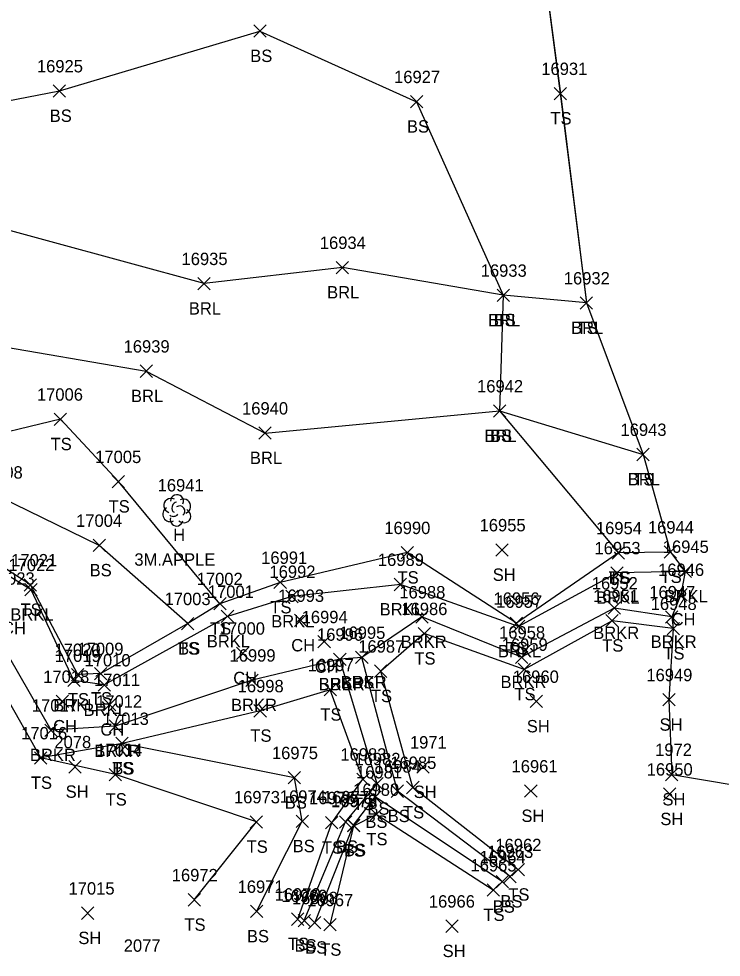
# Model space of a CAD drawing. Extents: x 1482574 to 1485769, y 580696 to 595649.
# Drawn here: x 1485016 to 1485129.5, y 582871.1 to 583022.8 of the extents above; entities that cross this region are included whole.
import ezdxf

# ---------------------------------------------------------------- set-up
doc = ezdxf.new("R2010")
doc.units = 0
for name, color, linetype in [('L_A', 7, 'Continuous'), ('L_C', 7, 'Continuous'), ('L_I', 7, 'Continuous'), ('L_TIC', 7, 'Continuous'), ('LABL', 7, 'Continuous'), ('LAWE', 7, 'Continuous'), ('LELB', 7, 'Continuous'), ('LSOGP', 7, 'Continuous'), ('LTD', 7, 'Continuous')]:
    doc.layers.add(name, color=color, linetype=linetype)

msp = doc.modelspace()

# ---------------------------------------------------------------- linework, layer by layer
at = {"layer": 'L_TIC'}
for points in [[(1485053.96, 583019.83), (1485055.96, 583021.83)], [(1485055.96, 583019.83), (1485053.96, 583021.83)], [(1485021.56, 583010.15), (1485023.56, 583012.15)], [(1485023.56, 583010.15), (1485021.56, 583012.15)], [(1485102.51, 583009.73), (1485104.51, 583011.73)], [(1485104.51, 583009.73), (1485102.51, 583011.73)], [(1485079.29, 583008.42), (1485081.29, 583010.42)], [(1485081.29, 583008.42), (1485079.29, 583010.42)], [(1485067.29, 582981.61), (1485069.29, 582983.61)], [(1485069.29, 582981.61), (1485067.29, 582983.61)], [(1485044.94, 582979.01), (1485046.94, 582981.01)], [(1485046.94, 582979.01), (1485044.94, 582981.01)], [(1485093.29, 582977.12), (1485095.29, 582979.12)], [(1485095.29, 582977.12), (1485093.29, 582979.12)], [(1485093.29, 582977.12), (1485095.29, 582979.12)], [(1485095.29, 582977.12), (1485093.29, 582979.12)], [(1485106.72, 582975.88), (1485108.72, 582977.88)], [(1485108.72, 582975.88), (1485106.72, 582977.88)], [(1485106.72, 582975.88), (1485108.72, 582977.88)], [(1485108.72, 582975.88), (1485106.72, 582977.88)], [(1485035.59, 582964.86), (1485037.59, 582966.86)], [(1485037.59, 582964.86), (1485035.59, 582966.86)], [(1485021.73, 582957.09), (1485023.73, 582959.09)], [(1485023.73, 582957.09), (1485021.73, 582959.09)], [(1485092.7, 582958.43), (1485094.7, 582960.43)], [(1485094.7, 582958.43), (1485092.7, 582960.43)], [(1485092.7, 582958.43), (1485094.7, 582960.43)], [(1485094.7, 582958.43), (1485092.7, 582960.43)], [(1485054.81, 582954.85), (1485056.81, 582956.85)], [(1485056.81, 582954.85), (1485054.81, 582956.85)], [(1485115.88, 582951.39), (1485117.88, 582953.39)], [(1485117.88, 582951.39), (1485115.88, 582953.39)], [(1485115.88, 582951.39), (1485117.88, 582953.39)], [(1485117.88, 582951.39), (1485115.88, 582953.39)], [(1485031.1, 582947.01), (1485033.1, 582949.01)], [(1485033.1, 582947.01), (1485031.1, 582949.01)], [(1485028.01, 582936.7), (1485030.01, 582938.7)], [(1485030.01, 582936.7), (1485028.01, 582938.7)], [(1485093.1, 582935.97), (1485095.1, 582937.97)], [(1485095.1, 582935.97), (1485093.1, 582937.97)], [(1485077.79, 582935.53), (1485079.79, 582937.53)], [(1485079.79, 582935.53), (1485077.79, 582937.53)], [(1485111.9, 582935.5), (1485113.9, 582937.5)], [(1485113.9, 582935.5), (1485111.9, 582937.5)], [(1485111.9, 582935.5), (1485113.9, 582937.5)], [(1485113.9, 582935.5), (1485111.9, 582937.5)], [(1485120.3, 582935.63), (1485122.3, 582937.63)], [(1485122.3, 582935.63), (1485120.3, 582937.63)], [(1485111.68, 582932.26), (1485113.68, 582934.26)], [(1485113.68, 582932.26), (1485111.68, 582934.26)], [(1485122.7, 582932.49), (1485124.7, 582934.49)], [(1485124.7, 582932.49), (1485122.7, 582934.49)], [(1485016.87, 582930.31), (1485018.87, 582932.31)], [(1485018.87, 582930.31), (1485016.87, 582932.31)], [(1485057.24, 582930.71), (1485059.24, 582932.71)], [(1485059.24, 582930.71), (1485057.24, 582932.71)], [(1485076.68, 582930.38), (1485078.68, 582932.38)], [(1485078.68, 582930.38), (1485076.68, 582932.38)], [(1485016.99, 582929.54), (1485018.99, 582931.54)], [(1485018.99, 582929.54), (1485016.99, 582931.54)], [(1485059.14, 582928.44), (1485061.14, 582930.44)], [(1485061.14, 582928.44), (1485059.14, 582930.44)], [(1485122.01, 582928.76), (1485124.01, 582930.76)], [(1485124.01, 582928.76), (1485122.01, 582930.76)], [(1485047.5, 582927.28), (1485049.5, 582929.28)], [(1485049.5, 582927.28), (1485047.5, 582929.28)], [(1485047.5, 582927.28), (1485049.5, 582929.28)], [(1485049.5, 582927.28), (1485047.5, 582929.28)], [(1485048.73, 582925.22), (1485050.73, 582927.22)], [(1485050.73, 582925.22), (1485048.73, 582927.22)], [(1485080.14, 582925.13), (1485082.14, 582927.13)], [(1485082.14, 582925.13), (1485080.14, 582927.13)], [(1485111.24, 582926.58), (1485113.24, 582928.58)], [(1485113.24, 582926.58), (1485111.24, 582928.58)], [(1485120.53, 582925.14), (1485122.53, 582927.14)], [(1485122.53, 582925.14), (1485120.53, 582927.14)], [(1485042.31, 582924.05), (1485044.31, 582926.05)], [(1485044.31, 582924.05), (1485042.31, 582926.05)], [(1485042.31, 582924.05), (1485044.31, 582926.05)], [(1485044.31, 582924.05), (1485042.31, 582926.05)], [(1485060.54, 582924.57), (1485062.54, 582926.57)], [(1485062.54, 582924.57), (1485060.54, 582926.57)], [(1485095.41, 582924.11), (1485097.41, 582926.11)], [(1485097.41, 582924.11), (1485095.41, 582926.11)], [(1485095.77, 582923.61), (1485097.77, 582925.61)], [(1485097.77, 582923.61), (1485095.77, 582925.61)], [(1485110.87, 582924.53), (1485112.87, 582926.53)], [(1485112.87, 582924.53), (1485110.87, 582926.53)], [(1485080.52, 582922.44), (1485082.52, 582924.44)], [(1485082.52, 582922.44), (1485080.52, 582924.44)], [(1485120.76, 582923.26), (1485122.76, 582925.26)], [(1485122.76, 582923.26), (1485120.76, 582925.26)], [(1485064.35, 582921.12), (1485066.35, 582923.12)], [(1485066.35, 582921.12), (1485064.35, 582923.12)], [(1485051.17, 582919.27), (1485053.17, 582921.27)], [(1485053.17, 582919.27), (1485051.17, 582921.27)], [(1485066.88, 582918.29), (1485068.88, 582920.29)], [(1485068.88, 582918.29), (1485066.88, 582920.29)], [(1485066.88, 582918.29), (1485068.88, 582920.29)], [(1485068.88, 582918.29), (1485066.88, 582920.29)], [(1485070.44, 582918.59), (1485072.44, 582920.59)], [(1485072.44, 582918.59), (1485070.44, 582920.59)], [(1485070.44, 582918.59), (1485072.44, 582920.59)], [(1485072.44, 582918.59), (1485070.44, 582920.59)], [(1485096.26, 582918.63), (1485098.26, 582920.63)], [(1485098.26, 582918.63), (1485096.26, 582920.63)], [(1485073.5, 582916.37), (1485075.5, 582918.37)], [(1485075.5, 582916.37), (1485073.5, 582918.37)], [(1485073.5, 582916.37), (1485075.5, 582918.37)], [(1485075.5, 582916.37), (1485073.5, 582918.37)], [(1485096.69, 582916.66), (1485098.69, 582918.66)], [(1485098.69, 582916.66), (1485096.69, 582918.66)], [(1485023.91, 582914.87), (1485025.91, 582916.87)], [(1485025.91, 582914.87), (1485023.91, 582916.87)], [(1485024.52, 582915.83), (1485026.52, 582917.83)], [(1485026.52, 582915.83), (1485024.52, 582917.83)], [(1485028.24, 582915.98), (1485030.24, 582917.98)], [(1485030.24, 582915.98), (1485028.24, 582917.98)], [(1485052.71, 582914.91), (1485054.71, 582916.91)], [(1485054.71, 582914.91), (1485052.71, 582916.91)], [(1485028.82, 582914.14), (1485030.82, 582916.14)], [(1485030.82, 582914.14), (1485028.82, 582916.14)], [(1485065.33, 582913.37), (1485067.33, 582915.37)], [(1485067.33, 582913.37), (1485065.33, 582915.37)], [(1485065.33, 582913.37), (1485067.33, 582915.37)], [(1485067.33, 582913.37), (1485065.33, 582915.37)], [(1485022.05, 582911.48), (1485024.05, 582913.48)], [(1485024.05, 582911.48), (1485022.05, 582913.48)], [(1485098.62, 582911.48), (1485100.62, 582913.48)], [(1485100.62, 582911.48), (1485098.62, 582913.48)], [(1485120.07, 582911.75), (1485122.07, 582913.75)], [(1485122.07, 582911.75), (1485120.07, 582913.75)], [(1485029.69, 582910.95), (1485031.69, 582912.95)], [(1485031.69, 582910.95), (1485029.69, 582912.95)], [(1485054.01, 582909.96), (1485056.01, 582911.96)], [(1485056.01, 582909.96), (1485054.01, 582911.96)], [(1485030.6, 582907.48), (1485032.6, 582909.48)], [(1485032.6, 582907.48), (1485030.6, 582909.48)], [(1485020.21, 582906.83), (1485022.21, 582908.83)], [(1485022.21, 582906.83), (1485020.21, 582908.83)], [(1485031.68, 582904.68), (1485033.68, 582906.68)], [(1485033.68, 582904.68), (1485031.68, 582906.68)], [(1485031.68, 582904.68), (1485033.68, 582906.68)], [(1485033.68, 582904.68), (1485031.68, 582906.68)], [(1485018.54, 582902.35), (1485020.54, 582904.35)], [(1485020.54, 582902.35), (1485018.54, 582904.35)], [(1485018.54, 582902.35), (1485020.54, 582904.35)], [(1485020.54, 582902.35), (1485018.54, 582904.35)], [(1485024.08, 582900.91), (1485026.08, 582902.91)], [(1485026.08, 582900.91), (1485024.08, 582902.91)], [(1485080.33, 582900.87), (1485082.33, 582902.87)], [(1485082.33, 582900.87), (1485080.33, 582902.87)], [(1485030.62, 582899.65), (1485032.62, 582901.65)], [(1485032.62, 582899.65), (1485030.62, 582901.65)], [(1485120.53, 582899.67), (1485122.53, 582901.67)], [(1485122.53, 582899.67), (1485120.53, 582901.67)], [(1485059.54, 582899.15), (1485061.54, 582901.15)], [(1485061.54, 582899.15), (1485059.54, 582901.15)], [(1485070.61, 582898.91), (1485072.61, 582900.91)], [(1485072.61, 582898.91), (1485070.61, 582900.91)], [(1485072.89, 582898.17), (1485074.89, 582900.17)], [(1485074.89, 582898.17), (1485072.89, 582900.17)], [(1485072.89, 582898.17), (1485074.89, 582900.17)], [(1485074.89, 582898.17), (1485072.89, 582900.17)], [(1485076.18, 582896.98), (1485078.18, 582898.98)], [(1485078.18, 582896.98), (1485076.18, 582898.98)], [(1485078.68, 582897.57), (1485080.68, 582899.57)], [(1485080.68, 582897.57), (1485078.68, 582899.57)], [(1485097.75, 582897), (1485099.75, 582899)], [(1485099.75, 582897), (1485097.75, 582899)], [(1485120.19, 582896.49), (1485122.19, 582898.49)], [(1485122.19, 582896.49), (1485120.19, 582898.49)], [(1485072.57, 582896.04), (1485074.57, 582898.04)], [(1485074.57, 582896.04), (1485072.57, 582898.04)], [(1485072.57, 582896.04), (1485074.57, 582898.04)], [(1485074.57, 582896.04), (1485072.57, 582898.04)], [(1485072.76, 582893.23), (1485074.76, 582895.23)], [(1485074.76, 582893.23), (1485072.76, 582895.23)], [(1485072.76, 582893.23), (1485074.76, 582895.23)], [(1485074.76, 582893.23), (1485072.76, 582895.23)], [(1485053.41, 582892.01), (1485055.41, 582894.01)], [(1485055.41, 582892.01), (1485053.41, 582894.01)], [(1485060.82, 582892.11), (1485062.82, 582894.11)], [(1485062.82, 582892.11), (1485060.82, 582894.11)], [(1485065.58, 582891.87), (1485067.58, 582893.87)], [(1485067.58, 582891.87), (1485065.58, 582893.87)], [(1485067.81, 582892.01), (1485069.81, 582894.01)], [(1485069.81, 582892.01), (1485067.81, 582894.01)], [(1485069.1, 582891.46), (1485071.1, 582893.46)], [(1485071.1, 582891.46), (1485069.1, 582893.46)], [(1485069.12, 582891.39), (1485071.12, 582893.39)], [(1485071.12, 582891.39), (1485069.12, 582893.39)], [(1485095.7, 582884.28), (1485097.7, 582886.28)], [(1485097.7, 582884.28), (1485095.7, 582886.28)], [(1485094.4, 582883.18), (1485096.4, 582885.18)], [(1485096.4, 582883.18), (1485094.4, 582885.18)], [(1485093.15, 582882.33), (1485095.15, 582884.33)], [(1485095.15, 582882.33), (1485093.15, 582884.33)], [(1485091.68, 582881), (1485093.68, 582883)], [(1485093.68, 582881), (1485091.68, 582883)], [(1485043.36, 582879.41), (1485045.36, 582881.41)], [(1485045.36, 582879.41), (1485043.36, 582881.41)], [(1485026.14, 582877.26), (1485028.14, 582879.26)], [(1485028.14, 582877.26), (1485026.14, 582879.26)], [(1485053.43, 582877.54), (1485055.43, 582879.54)], [(1485055.43, 582877.54), (1485053.43, 582879.54)], [(1485060.07, 582876.29), (1485062.07, 582878.29)], [(1485062.07, 582876.29), (1485060.07, 582878.29)], [(1485061.13, 582876.05), (1485063.13, 582878.05)], [(1485063.13, 582876.05), (1485061.13, 582878.05)], [(1485062.83, 582875.71), (1485064.83, 582877.71)], [(1485064.83, 582875.71), (1485062.83, 582877.71)], [(1485065.3, 582875.38), (1485067.3, 582877.38)], [(1485067.3, 582875.38), (1485065.3, 582877.38)], [(1485085.01, 582875.16), (1485087.01, 582877.16)], [(1485087.01, 582875.16), (1485085.01, 582877.16)]]:
    msp.add_lwpolyline(points, dxfattribs=at)
at = {"layer": 'LABL'}
msp.add_lwpolyline([(1485107.72, 582976.88), (1485094.29, 582978.12), (1485068.29, 582982.61), (1485045.94, 582980.01), (1485007.9, 582990.37), (1485001, 582981.38), (1485010.19, 582970.36), (1485036.59, 582965.86), (1485055.81, 582955.85), (1485093.7, 582959.43), (1485116.88, 582952.39)], dxfattribs=at)
at = {"layer": 'LAWE'}
for points in [[(1485123.7, 582933.49), (1485112.68, 582933.26), (1485096.77, 582924.61), (1485077.68, 582931.38), (1485060.14, 582929.44), (1485049.73, 582926.22), (1485029.82, 582915.14), (1485024.91, 582915.87), (1485017.99, 582930.54), (1485007.2, 582937.17), (1485001.22, 582943.38), (1484992.98, 582957.36), (1484981.1, 582966.08), (1484969.65, 582970.81), (1484966.84, 582974.91), (1484969.87, 582981.75), (1484967.99, 582987.69), (1484963.16, 582993.41), (1484943.08, 582999.77)], [(1485121.53, 582926.14), (1485112.24, 582927.58), (1485097.26, 582919.63), (1485081.14, 582926.13), (1485071.44, 582919.59), (1485067.88, 582919.29), (1485053.71, 582915.91), (1485031.6, 582908.48), (1485021.21, 582907.83), (1485010.94, 582925.67), (1485004.69, 582933.37), (1484995.82, 582942.92), (1484986.83, 582954.25), (1484977.2, 582963.34), (1484963.68, 582969.01), (1484961.04, 582975.02), (1484964.44, 582984), (1484958.58, 582987.66), (1484946.85, 582991.58)]]:
    msp.add_lwpolyline(points, dxfattribs=at)
at = {"layer": 'LELB'}
for points in [[(1485100.1, 583036.87), (1485103.51, 583010.73), (1485107.72, 582976.88), (1485116.88, 582952.39), (1485121.3, 582936.63), (1485112.9, 582936.5), (1485096.41, 582925.11), (1485078.79, 582936.53), (1485058.24, 582931.71), (1485048.5, 582928.28), (1485032.1, 582948.01), (1485022.73, 582958.09), (1485007.54, 582954.43), (1484998.15, 582959.34)], [(1484952.16, 583010.58), (1484991.93, 583005.23), (1485022.56, 583011.15), (1485054.96, 583020.83), (1485080.29, 583009.42), (1485094.29, 582978.12), (1485093.7, 582959.43), (1485112.9, 582936.5)], [(1485048.5, 582928.28), (1485043.31, 582925.05), (1485029.24, 582916.98), (1485025.52, 582916.83), (1485017.87, 582931.31), (1485007.46, 582938.06), (1485003.43, 582945.8), (1484998.15, 582959.34), (1484981.68, 582967.5), (1484970.06, 582971.15), (1484968.16, 582975.1), (1484970.87, 582981.38), (1484969.06, 582988.39), (1484964.08, 582995.64), (1484942.52, 583002.84)], [(1485066.33, 582914.37), (1485055.01, 582910.96), (1485032.68, 582905.68), (1485019.54, 582903.35), (1485007.57, 582924.48), (1485005.74, 582928.29), (1485002.98, 582932.23), (1484994.58, 582942.15), (1484985.02, 582952.34), (1484976.6, 582962.37), (1484961.88, 582967.48), (1484960.2, 582975.01), (1484963.54, 582983.65), (1484958.19, 582986.03), (1484945.11, 582987.82)], [(1485043.31, 582925.05), (1485029.01, 582937.7), (1485012.95, 582945.5), (1485003.43, 582945.8)], [(1485121.76, 582924.26), (1485111.87, 582925.53), (1485097.69, 582917.66), (1485081.52, 582923.44), (1485074.5, 582917.37)], [(1485095.4, 582884.18), (1485077.18, 582897.98), (1485071.44, 582919.59)], [(1485062.13, 582877.05), (1485068.81, 582893.01), (1485073.89, 582899.17), (1485067.88, 582919.29)], [(1485096.7, 582885.28), (1485079.68, 582898.57), (1485074.5, 582917.37)], [(1485061.07, 582877.29), (1485066.58, 582892.87), (1485071.61, 582899.91), (1485066.33, 582914.37)], [(1485054.43, 582878.54), (1485061.82, 582893.11), (1485060.54, 582900.15), (1485032.68, 582905.68)], [(1485044.36, 582880.41), (1485054.41, 582893.01), (1485031.62, 582900.65), (1485019.54, 582903.35)], [(1485094.15, 582883.33), (1485073.57, 582897.04), (1485073.89, 582899.17)], [(1485063.83, 582876.71), (1485070.1, 582892.46), (1485073.57, 582897.04)], [(1485066.3, 582876.38), (1485070.12, 582892.39), (1485073.76, 582894.23)], [(1485092.68, 582882), (1485073.76, 582894.23)]]:
    msp.add_lwpolyline(points, dxfattribs=at)
at = {"layer": 'LSOGP'}
msp.add_lwpolyline([(1485090.21, 583174.78), (1485087.62, 583138.61), (1485091.33, 583101.23), (1485097.58, 583070.83), (1485100.1, 583036.88), (1485103.52, 583010.73), (1485107.72, 582976.88), (1485116.88, 582952.4), (1485121.3, 582936.63), (1485123.7, 582933.5), (1485123.01, 582929.76), (1485121.53, 582926.14), (1485121.76, 582924.27), (1485121.07, 582912.76), (1485121.53, 582900.67), (1485163.43, 582893.59), (1485198.54, 582893.35), (1485231.28, 582875.52)], dxfattribs=at)
at = {"layer": 'LTD'}
msp.add_line((1485041.51, 582943.42), (1485041.51, 582943.42), dxfattribs=at)
msp.add_line((1485041.51, 582943.42), (1485041.51, 582943.42), dxfattribs=at)
msp.add_arc((1485041.56, 582944.85), 1.05, 335.5272, 180.9563, dxfattribs=at)
for centre, major_axis, ratio, start_param, end_param in [((1485040.72, 582944.08), (1.21, -0.51), 0.895232, 1.570796, 4.712389), ((1485042.55, 582944), (-1.14, -0.48), 0.949671, 1.570796, 4.712389), ((1485041.3, 582943.87), (-0.208, -0.792), 0.645439, 3.141593, 6.283185), ((1485042.01, 582943.25), (-0.5, 0.667), 0.989748, 3.141593, 6.283185), ((1485040.43, 582942.71), (0.58, -1.04), 0.959034, 3.141593, 6.283185), ((1485041.06, 582942.67), (-0.625, -0.083), 0.423636, 0, 3.141593), ((1485042.51, 582942.58), (-1.09, 0.79), 0.841452, 1.570796, 4.712389), ((1485041.51, 582941.92), (0.26, 1.06), 0.942809, 1.570796, 4.712389)]:
    msp.add_ellipse(centre, major_axis=major_axis, ratio=ratio, start_param=start_param, end_param=end_param, dxfattribs=at)

# ---------------------------------------------------------------- texts
at = {"layer": 'L_A'}
for s, p in [('BS', (1485053.4, 583015.83)), ('BS', (1485021, 583006.15)), ('TS', (1485101.92, 583005.73)), ('BS', (1485078.73, 583004.42)), ('BRL', (1485065.83, 582977.61)), ('BRL', (1485043.48, 582975.01)), ('BRL', (1485091.83, 582973.12)), ('BS', (1485092.73, 582973.12)), ('BRL', (1485105.26, 582971.88)), ('TS', (1485106.13, 582971.88)), ('BRL', (1485034.13, 582960.86)), ('BRL', (1485091.24, 582954.43)), ('BS', (1485092.14, 582954.43)), ('TS', (1485021.14, 582953.09)), ('BRL', (1485053.35, 582950.85)), ('BRL', (1485114.42, 582947.39)), ('TS', (1485115.29, 582947.39)), ('TS', (1485030.51, 582943.01)), ('H', (1485040.95, 582938.42)), ('BS', (1485027.45, 582932.7)), ('TS', (1485077.2, 582931.53)), ('SH', (1485092.59, 582931.97)), ('TS', (1485111.31, 582931.5)), ('BS', (1485111.35, 582931.5)), ('TS', (1485119.71, 582931.63)), ('BRKL', (1485109.32, 582928.26)), ('BRKL', (1485120.35, 582928.49)), ('TS', (1485056.65, 582926.71)), ('BRKL', (1485014.64, 582925.54)), ('TS', (1485016.28, 582926.31)), ('BRKL', (1485074.32, 582926.38)), ('BRKL', (1485056.79, 582924.44)), ('CH', (1485121.5, 582924.76)), ('CH', (1485013.29, 582923.35)), ('TS', (1485046.91, 582923.28)), ('TS', (1485046.91, 582923.28)), ('BRKR', (1485108.83, 582922.58)), ('BRKL', (1485046.38, 582921.22)), ('CH', (1485060.03, 582920.57)), ('BRKR', (1485077.73, 582921.13)), ('TS', (1485110.28, 582920.53)), ('BRKR', (1485118.12, 582921.14)), ('TS', (1485041.72, 582920.05)), ('BS', (1485041.75, 582920.05)), ('BRKL', (1485093.42, 582919.61)), ('TS', (1485094.82, 582920.11)), ('TS', (1485120.17, 582919.26)), ('TS', (1485079.93, 582918.44)), ('CH', (1485063.84, 582917.12)), ('CH', (1485050.66, 582915.27)), ('BRKR', (1485068.03, 582914.59)), ('BS', (1485069.88, 582914.59)), ('BRKR', (1485093.85, 582914.63)), ('BRKR', (1485064.47, 582914.29)), ('BS', (1485066.33, 582914.29)), ('TS', (1485023.93, 582911.83)), ('TS', (1485027.65, 582911.98)), ('TS', (1485072.91, 582912.37)), ('TS', (1485072.91, 582912.37)), ('TS', (1485096.1, 582912.66)), ('BRKL', (1485021.56, 582910.87)), ('BRKL', (1485026.47, 582910.14)), ('BRKR', (1485050.3, 582910.91)), ('TS', (1485064.74, 582909.37)), ('TS', (1485064.74, 582909.37)), ('CH', (1485021.54, 582907.48)), ('CH', (1485029.18, 582906.95)), ('SH', (1485098.1, 582907.48)), ('SH', (1485119.55, 582907.75)), ('TS', (1485053.42, 582905.96)), ('BRKR', (1485017.8, 582902.83)), ('BRKR', (1485028.2, 582903.48)), ('TS', (1485031.09, 582900.68)), ('BS', (1485031.12, 582900.68)), ('TS', (1485017.95, 582898.35)), ('TS', (1485017.95, 582898.35)), ('SH', (1485023.57, 582896.91)), ('SH', (1485079.82, 582896.87)), ('TS', (1485030.03, 582895.65)), ('BS', (1485058.99, 582895.15)), ('TS', (1485070.02, 582894.91)), ('SH', (1485120.02, 582895.67)), ('BS', (1485072.33, 582894.17)), ('BS', (1485072.33, 582894.17)), ('TS', (1485078.09, 582893.57)), ('BS', (1485072.01, 582892.04)), ('BS', (1485072.01, 582892.04)), ('BS', (1485075.62, 582892.98)), ('SH', (1485097.23, 582893)), ('SH', (1485119.68, 582892.49)), ('TS', (1485072.17, 582889.23)), ('TS', (1485072.17, 582889.23)), ('TS', (1485052.82, 582888.01)), ('BS', (1485060.26, 582888.11)), ('TS', (1485064.99, 582887.87)), ('BS', (1485067.25, 582888.01)), ('TS', (1485068.53, 582887.39)), ('BS', (1485068.54, 582887.46)), ('TS', (1485095.11, 582880.28)), ('BS', (1485092.59, 582878.33)), ('BS', (1485093.84, 582879.18)), ('TS', (1485091.09, 582877)), ('TS', (1485042.77, 582875.41)), ('BS', (1485052.87, 582873.54)), ('SH', (1485025.63, 582873.26)), ('TS', (1485059.48, 582872.29)), ('BS', (1485060.57, 582872.05)), ('BS', (1485062.27, 582871.71)), ('TS', (1485064.71, 582871.38)), ('SH', (1485084.49, 582871.16))]:
    msp.add_text(s, height=2, dxfattribs=at).set_placement(p)
at = {"layer": 'L_C'}
msp.add_text('3M.APPLE', height=2, dxfattribs=at).set_placement((1485034.68, 582934.42))
at = {"layer": 'L_I'}
for s, p in [('16925', (1485018.93, 583014.15)), ('16931', (1485100.44, 583013.73)), ('16927', (1485076.65, 583012.42)), ('16934', (1485064.65, 582985.61)), ('16935', (1485042.3, 582983.01)), ('16933', (1485090.65, 582981.12)), ('16933', (1485090.65, 582981.12)), ('16932', (1485104.08, 582979.88)), ('16932', (1485104.08, 582979.88)), ('16939', (1485032.94, 582968.86)), ('16942', (1485090.06, 582962.43)), ('16942', (1485090.06, 582962.43)), ('17006', (1485018.93, 582961.09)), ('16940', (1485052.08, 582958.85)), ('16943', (1485113.24, 582955.39)), ('16943', (1485113.24, 582955.39)), ('17005', (1485028.35, 582951.01)), ('17008', (1485009.2, 582948.5)), ('16941', (1485038.44, 582946.42)), ('17004', (1485025.26, 582940.7)), ('16990', (1485075.07, 582939.53)), ('16955', (1485090.47, 582939.97)), ('16954', (1485109.27, 582939.5)), ('16954', (1485109.27, 582939.5)), ('16944', (1485117.67, 582939.63)), ('16953', (1485109.04, 582936.26)), ('16945', (1485120.07, 582936.49)), ('17021', (1485014.77, 582934.31)), ('16991', (1485055.17, 582934.71)), ('16989', (1485074.03, 582934.38)), ('17022', (1485014.32, 582933.54)), ('16946', (1485119.32, 582932.76)), ('17023', (1485011.13, 582931.35)), ('17002', (1485044.75, 582931.28)), ('17002', (1485044.75, 582931.28)), ('16992', (1485056.51, 582932.44)), ('16952', (1485108.6, 582930.58)), ('17001', (1485046.55, 582929.22)), ('16993', (1485057.9, 582928.57)), ('16988', (1485077.5, 582929.13)), ('16956', (1485092.72, 582928.11)), ('16951', (1485108.8, 582928.53)), ('16947', (1485117.89, 582929.14)), ('17003', (1485039.56, 582928.05)), ('17003', (1485039.56, 582928.05)), ('16957', (1485093.14, 582927.61)), ('16948', (1485118.12, 582927.26)), ('16994', (1485061.71, 582925.12)), ('16986', (1485077.83, 582926.44)), ('17000', (1485048.34, 582923.27)), ('16996', (1485064.19, 582922.29)), ('16996', (1485064.19, 582922.29)), ('16995', (1485067.8, 582922.59)), ('16995', (1485067.8, 582922.59)), ('16958', (1485093.62, 582922.63)), ('16959', (1485094.04, 582920.66)), ('17020', (1485021.77, 582919.83)), ('17009', (1485025.48, 582919.98)), ('16987', (1485070.86, 582920.37)), ('16987', (1485070.86, 582920.37)), ('17019', (1485021.8, 582918.87)), ('17010', (1485026.63, 582918.14)), ('16999', (1485050.06, 582918.91)), ('16997', (1485062.69, 582917.37)), ('16997', (1485062.69, 582917.37)), ('17018', (1485019.95, 582915.48)), ('17011', (1485028.15, 582914.95)), ('16960', (1485095.84, 582915.48)), ('16949', (1485117.42, 582915.75)), ('16998', (1485051.37, 582913.96)), ('17012', (1485028.5, 582911.48)), ('17017', (1485018.11, 582910.83)), ('17013', (1485029.58, 582908.68)), ('17013', (1485029.58, 582908.68)), ('17016', (1485016.38, 582906.35)), ('17016', (1485016.38, 582906.35)), ('2078', (1485021.75, 582904.91)), ('1971', (1485079.21, 582904.87)), ('17014', (1485028.52, 582903.65)), ('16975', (1485056.91, 582903.15)), ('16983', (1485067.97, 582902.91)), ('1972', (1485118.84, 582903.67)), ('16982', (1485070.25, 582902.17)), ('16982', (1485070.25, 582902.17)), ('16984', (1485073.54, 582900.98)), ('16985', (1485076.04, 582901.57)), ('16961', (1485095.63, 582901)), ('16981', (1485070.5, 582900.04)), ('16981', (1485070.5, 582900.04)), ('16950', (1485117.47, 582900.49)), ('16980', (1485070.04, 582897.23)), ('16980', (1485070.04, 582897.23)), ('16973', (1485050.77, 582896.01)), ('16974', (1485058.19, 582896.11)), ('16976', (1485062.89, 582895.87)), ('16977', (1485065.17, 582896.01)), ('16978', (1485066.47, 582895.46)), ('16979', (1485066.47, 582895.39)), ('16963', (1485091.71, 582887.18)), ('16962', (1485093.02, 582888.28)), ('16964', (1485090.47, 582886.33)), ('16965', (1485089, 582885)), ('16972', (1485040.72, 582883.41)), ('17015', (1485024.04, 582881.26)), ('16971', (1485051.36, 582881.54)), ('16970', (1485057.34, 582880.29)), ('16969', (1485058.44, 582880.05)), ('16968', (1485060.14, 582879.71)), ('16967', (1485062.61, 582879.38)), ('16966', (1485082.27, 582879.16)), ('2077', (1485032.96, 582872.02))]:
    msp.add_text(s, height=2, dxfattribs=at).set_placement(p)

doc.saveas('drawing.dxf')
